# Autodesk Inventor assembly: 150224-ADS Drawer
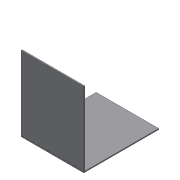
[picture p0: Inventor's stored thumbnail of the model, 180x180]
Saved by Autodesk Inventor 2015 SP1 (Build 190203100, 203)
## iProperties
Created: 2015-02
Part Number: 150224-ADS Drawer
Description: 150224-ADS Drawer
Document SubType Name: Assembly
Designer: AS
RuleStatus: InUse
ILogicFactory: True
Author: AS
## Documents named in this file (3)
- C:\Users\adrian.salariu\Desktop\`tmp\150224\150224-ADS Drawer.iam
- C:\Users\adrian.salariu\Desktop\`tmp\150224\150224-ADS Master_Schublade.ipt
- C:\Users\adrian.salariu\Desktop\`tmp\150224\150224-ADS Master_Schublade 1.ipt
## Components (2 placed, 2 different names)
1. 150224-ADS Master_Schublade — Flush:4, Flush:2, Flush:3
2. 150224-ADS Master_Schublade 1 — Flush:4, Flush:2, Flush:3
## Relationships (3: Flush 3)
- Flush:4: 150224-ADS Master_Schublade ↔ 150224-ADS Master_Schublade 1
- Flush:2: 150224-ADS Master_Schublade ↔ 150224-ADS Master_Schublade 1
- Flush:3: 150224-ADS Master_Schublade ↔ 150224-ADS Master_Schublade 1
## Named parameters: Depth = 484 mm
